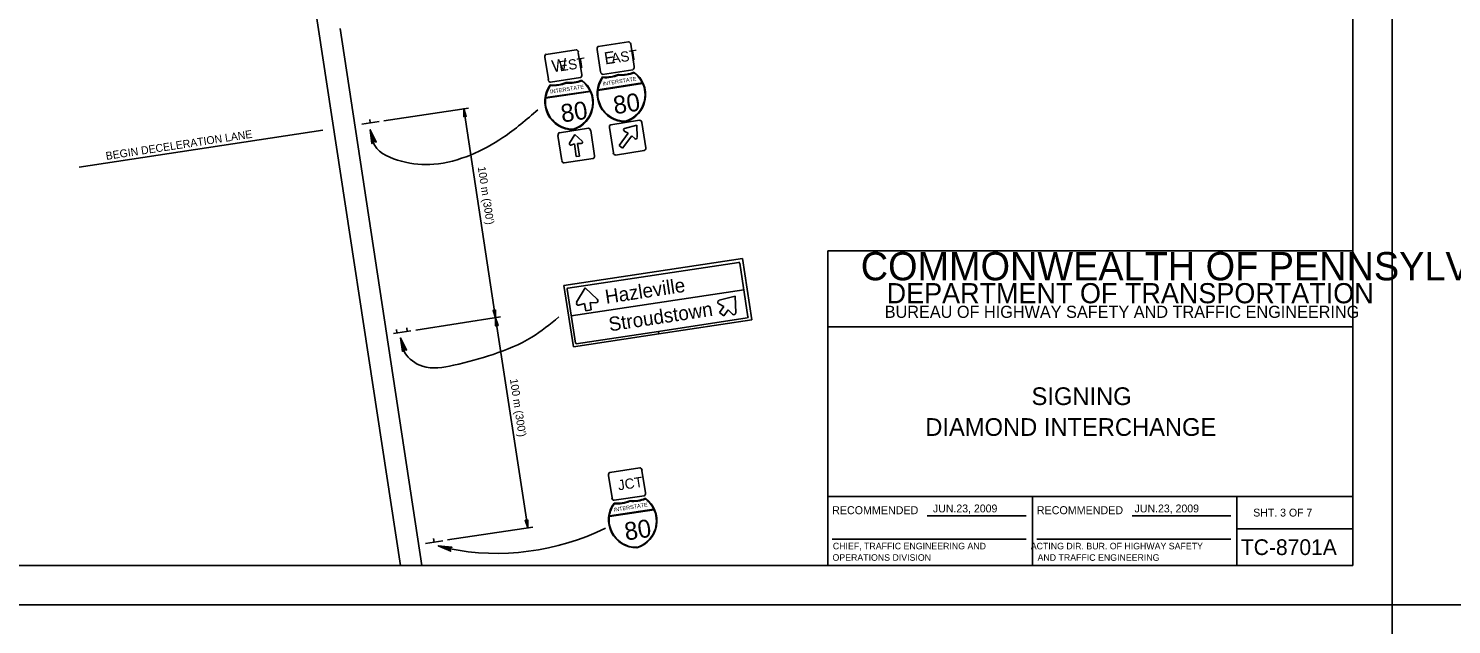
# Model space of a CAD drawing. Extents: x 640994 to 644422, y 298458 to 299646.
# Drawn here: x 642998 to 643540, y 299044 to 299271 of the extents above; entities that cross this region are included whole.
import ezdxf

# ---------------------------------------------------------------- set-up
doc = ezdxf.new("R2010")
doc.units = 0
for name, color, linetype in [('1', 7, 'Continuous'), ('2', 7, 'Continuous'), ('PLT-BNDY', 7, 'Continuous'), ('XCS-GRID-MIN', 7, 'Continuous')]:
    doc.layers.add(name, color=color, linetype=linetype)

msp = doc.modelspace()

# ---------------------------------------------------------------- linework, layer by layer
at = {"layer": '1'}
for p, q in [((643502.31, 299066.63), (643502.31, 299630.63)), ((643302.31, 299066.63), (643302.31, 299186.63)), ((643302.31, 299186.63), (643502.31, 299186.63)), ((643502.31, 299157.63), (643302.31, 299157.63)), ((643302.31, 299093), (643502.31, 299093)), ((643380.31, 299093), (643380.31, 299066.63)), ((643458.19, 299066.63), (643458.19, 299093)), ((643340.24, 299085.57), (643377.87, 299085.57)), ((643418.24, 299085.57), (643455.87, 299085.57)), ((643458.19, 299080.63), (643502.31, 299080.63)), ((643303.99, 299076.68), (643377.87, 299076.68)), ((643381.99, 299076.68), (643455.87, 299076.68)), ((643502.31, 299066.63), (642716.31, 299066.63)), ((642716.31, 299066.63), (643302.31, 299066.63))]:
    msp.add_line(p, q, dxfattribs=at)
at = {"layer": '2'}
for p, q in [((643102.81, 299307.63), (643139.56, 299066.63)), ((643116.56, 299271.38), (643147.69, 299066.63)), ((643195.06, 299261.5), (643206.56, 299263.25)), ((643207.31, 299262.25), (643208.69, 299253.75)), ((643215.81, 299254.88), (643214.56, 299263.38)), ((643214.94, 299264.5), (643226.44, 299266.25)), ((643227.31, 299265.38), (643228.56, 299256.88)), ((643195.94, 299251.88), (643194.56, 299260.38)), ((643201.56, 299257.13), (643201.56, 299257.13)), ((643221.56, 299260.13), (643221.56, 299260.13)), ((643208.19, 299252.63), (643196.69, 299250.88)), ((643208.69, 299251.38), (643208.69, 299251.38)), ((643228.06, 299255.63), (643216.56, 299253.88)), ((643216.69, 299252.63), (643216.69, 299252.63)), ((643222.56, 299253.63), (643222.56, 299253.63)), ((643228.56, 299254.5), (643228.56, 299254.5)), ((643194.81, 299244.75), (643211.94, 299247.38)), ((643211.81, 299247.5), (643194.94, 299245)), ((643196.81, 299249.63), (643196.81, 299249.63)), ((643202.69, 299250.5), (643202.69, 299250.5)), ((643231.69, 299250.63), (643214.81, 299248)), ((643214.81, 299247.75), (643231.81, 299250.38)), ((643133.31, 299236.13), (643165.56, 299241)), ((643175.81, 299161), (643163.69, 299240.75)), ((643204.06, 299241.75), (643204.06, 299241.75)), ((643223.94, 299244.75), (643223.94, 299244.75)), ((643131.44, 299235.88), (643124.81, 299234.88)), ((643128.06, 299235.38), (643127.94, 299236.63)), ((643219.69, 299234.63), (643230.69, 299236.38)), ((643231.56, 299235.5), (643233.06, 299225.88)), ((643017.19, 299218.5), (643110.06, 299232.63)), ((643122.19, 299234.38), (643122.19, 299234.38)), ((643201.06, 299221), (643199.56, 299230.63)), ((643200.19, 299231.63), (643211.19, 299233.38)), ((643203.94, 299227.63), (643205.94, 299231)), ((643205.94, 299231), (643203.94, 299227.63)), ((643205.94, 299231), (643208.81, 299228.38)), ((643208.81, 299228.38), (643205.94, 299231)), ((643212.06, 299232.5), (643213.44, 299222.88)), ((643220.69, 299224), (643219.19, 299233.63)), ((643226.31, 299231.5), (643222.94, 299226.75)), ((643224.19, 299225.75), (643227.69, 299230.5)), ((643224.81, 299232.25), (643226.31, 299231.5)), ((643229.56, 299234.5), (643224.94, 299233.25)), ((643226.06, 299229.75), (643226.06, 299229.75)), ((643227.69, 299230.5), (643228.81, 299229.38)), ((643229.69, 299229.75), (643229.56, 299234.5)), ((643205.81, 299227.38), (643204.44, 299226.88)), ((643204.44, 299226.88), (643205.81, 299227.38)), ((643206.56, 299222.5), (643205.81, 299227.38)), ((643205.81, 299227.38), (643206.56, 299222.5)), ((643208.44, 299227.5), (643207.06, 299227.5)), ((643207.06, 299227.5), (643207.81, 299222.75)), ((643207.81, 299222.75), (643207.06, 299227.5)), ((643207.06, 299227.5), (643208.44, 299227.5)), ((643232.44, 299224.88), (643221.44, 299223.13)), ((643222.94, 299226.75), (643224.19, 299225.75)), ((643212.94, 299221.75), (643201.94, 299220.13)), ((643207.81, 299222.75), (643206.56, 299222.5)), ((643206.56, 299222.5), (643207.81, 299222.75)), ((643269.81, 299183.63), (643201.81, 299173.38)), ((643203.31, 299172.38), (643268.44, 299182.13)), ((643268.81, 299181.88), (643271.94, 299161.38)), ((643273.44, 299160.25), (643269.81, 299183.63)), ((643201.81, 299173.38), (643205.44, 299150)), ((643206.19, 299151.38), (643203.06, 299172)), ((643204.56, 299161.88), (643270.31, 299171.75)), ((643209.94, 299172.5), (643206.69, 299167)), ((643209.94, 299172.5), (643206.69, 299167)), ((643214.56, 299168.13), (643209.94, 299172.5)), ((643214.56, 299168.13), (643209.94, 299172.5)), ((643207.56, 299165.88), (643209.69, 299166.5)), ((643207.56, 299165.88), (643209.69, 299166.5)), ((643209.69, 299166.5), (643210.19, 299163.75)), ((643209.69, 299166.5), (643210.19, 299163.75)), ((643212.19, 299164.13), (643211.81, 299166.88)), ((643211.81, 299166.88), (643214.06, 299166.75)), ((643212.19, 299164.13), (643211.81, 299166.88)), ((643211.81, 299166.88), (643214.06, 299166.75)), ((643237.56, 299166.75), (643237.56, 299166.75)), ((643262.81, 299165.38), (643260.81, 299166.38)), ((643262.81, 299165.38), (643260.81, 299166.38)), ((643260.94, 299167.75), (643267.06, 299169.38)), ((643260.94, 299167.75), (643267.06, 299169.38)), ((643267.06, 299169.38), (643260.94, 299167.75)), ((643260.94, 299167.75), (643267.06, 299169.38)), ((643260.94, 299167.75), (643267.06, 299169.38)), ((643267.06, 299169.38), (643260.94, 299167.75)), ((643261.06, 299163.13), (643262.81, 299165.38)), ((643261.06, 299163.13), (643262.81, 299165.38)), ((643267.06, 299169.38), (643267.31, 299163)), ((643267.06, 299169.38), (643267.31, 299163)), ((643145.44, 299156.38), (643177.69, 299161.38)), ((643188.06, 299081), (643175.81, 299161)), ((643210.19, 299163.75), (643212.19, 299164.13)), ((643210.19, 299163.75), (643212.19, 299164.13)), ((643271.69, 299161), (643237.87, 299155.87)), ((643238.02, 299154.91), (643273.44, 299160.25)), ((643262.81, 299161.88), (643261.06, 299163.13)), ((643262.81, 299161.88), (643261.06, 299163.13)), ((643264.44, 299164.13), (643262.81, 299161.88)), ((643264.44, 299164.13), (643262.81, 299161.88)), ((643266.06, 299162.5), (643264.44, 299164.13)), ((643266.06, 299162.5), (643264.44, 299164.13)), ((643266.06, 299162.5), (643266.06, 299162.5)), ((643134.31, 299154.75), (643134.31, 299154.75)), ((643143.56, 299156.13), (643136.94, 299155.13)), ((643138.19, 299155.38), (643138.06, 299156.63)), ((643142.19, 299155.88), (643142.06, 299157.25)), ((643205.44, 299150), (643238.02, 299154.91)), ((643237.87, 299155.87), (643206.56, 299151.13)), ((643237.87, 299155.87), (643238.02, 299154.91)), ((643238.02, 299154.91), (643237.87, 299155.87)), ((643220.19, 299092.5), (643218.81, 299101)), ((643219.31, 299102.13), (643230.81, 299103.88)), ((643231.56, 299102.88), (643232.94, 299094.38)), ((643225.81, 299097.63), (643225.81, 299097.63)), ((643232.44, 299093.25), (643220.94, 299091.5)), ((643221.06, 299090.25), (643221.06, 299090.25)), ((643226.94, 299091.13), (643226.94, 299091.13)), ((643232.94, 299092), (643232.94, 299092)), ((643236.06, 299088.13), (643219.19, 299085.63)), ((643219.19, 299085.38), (643236.19, 299087.88)), ((643157.56, 299076.38), (643189.94, 299081.25)), ((643146.44, 299075), (643146.44, 299075)), ((643146.44, 299074.63), (643146.44, 299074.63)), ((643155.69, 299076), (643149.06, 299075)), ((643152.44, 299075.5), (643152.19, 299076.88))]:
    msp.add_line(p, q, dxfattribs=at)
for points in [[(643163.76, 299237.88), (643163.95, 299238.01), (643163.69, 299240.75), (643163.76, 299237.88), (643163.66, 299237.71), (643163.69, 299240.75), (643164.23, 299238.06), (643164.45, 299237.99), (643163.69, 299240.75), (643164.61, 299237.86), (643164.45, 299237.99)], [(643128.81, 299227.88), (643129.06, 299228.13), (643128.06, 299232.75), (643128.81, 299227.88), (643128.69, 299227.5), (643128.06, 299232.75), (643129.56, 299228.25), (643129.94, 299228.25), (643128.06, 299232.75), (643130.31, 299228), (643129.94, 299228.25)], [(643175.74, 299163.88), (643175.55, 299163.74), (643175.81, 299161), (643175.74, 299163.88), (643175.84, 299164.04), (643175.81, 299161), (643175.27, 299163.7), (643175.05, 299163.76), (643175.81, 299161), (643174.89, 299163.9), (643175.05, 299163.76)], [(643175.89, 299158.13), (643176.08, 299158.26), (643175.81, 299161), (643175.89, 299158.13), (643175.79, 299157.96), (643175.81, 299161), (643176.36, 299158.31), (643176.58, 299158.24), (643175.81, 299161), (643176.74, 299158.11), (643176.58, 299158.24)], [(643140.44, 299148.5), (643140.81, 299148.75), (643139.56, 299153.38), (643140.44, 299148.5), (643140.31, 299148.25), (643139.56, 299153.38), (643141.19, 299149), (643141.56, 299148.88), (643139.56, 299153.38), (643141.94, 299148.75), (643141.56, 299148.88)], [(643187.98, 299083.88), (643187.8, 299083.74), (643188.06, 299081), (643187.98, 299083.88), (643188.09, 299084.04), (643188.06, 299081), (643187.51, 299083.69), (643187.3, 299083.76), (643188.06, 299081), (643187.14, 299083.89), (643187.3, 299083.76)], [(643158.51, 299072.37), (643158.39, 299072.74), (643153.96, 299074.16), (643158.51, 299072.37), (643158.73, 299072.06), (643153.96, 299074.16), (643158.54, 299073.16), (643158.77, 299073.49), (643153.96, 299074.16), (643159.15, 299073.61), (643158.77, 299073.49)]]:
    msp.add_lwpolyline(points, dxfattribs=at)
for centre, radius, start, end in [((643203.86, 299263.04), 12.33, 264.4038, 292.9038), ((643203.86, 299263.04), 12.56, 264.6648, 292.3133), ((643202.3, 299243.04), 10.73, 286.7839, 53.6538), ((643202.3, 299243.04), 10.51, 25.4466, 52.9614), ((643225.23, 299246.52), 10.73, 143.6538, 270.5237), ((643225.23, 299246.52), 10.51, 144.3462, 171.8611), ((643217.79, 299265.16), 12.33, 264.4038, 292.9038), ((643217.79, 299265.16), 12.56, 264.9943, 292.6428), ((643223.79, 299266.07), 12.33, 264.4038, 292.9038), ((643223.79, 299266.07), 12.56, 264.6648, 292.3133), ((643222.23, 299246.07), 10.73, 286.7839, 53.6538), ((643222.23, 299246.07), 10.51, 25.4466, 52.9614), ((643205.3, 299243.49), 10.73, 143.6538, 270.5237), ((643205.3, 299243.49), 10.51, 144.3462, 171.8611), ((643197.86, 299262.12), 12.33, 264.4038, 292.9038), ((643197.86, 299262.12), 12.56, 264.9943, 292.6428), ((643202.3, 299243.04), 10.51, 286.7839, 24.1669), ((643225.23, 299246.52), 10.51, 173.1407, 270.5237), ((643222.23, 299246.07), 10.51, 286.7839, 24.1669), ((643205.3, 299243.49), 10.51, 173.1407, 270.5237), ((643225.07, 299232.74), 0.5, 103.9183, 245.5492), ((643229.19, 299229.7), 0.5, 225, 1.3737), ((643204.37, 299227.38), 0.46, 148.5129, 289.1785), ((643204.37, 299227.38), 0.46, 148.5129, 289.1785), ((643208.49, 299227.98), 0.46, 266.9014, 50.808), ((643208.49, 299227.98), 0.46, 266.9014, 50.8081), ((643268.53, 299181.93), 0.309, 7.3907, 98.4613), ((643203.39, 299172.11), 0.309, 98.9487, 188.5961), ((643207.4, 299166.56), 0.745, 148.5129, 289.1785), ((643207.4, 299166.56), 0.745, 148.5129, 289.1785), ((643214.08, 299167.54), 0.745, 266.9014, 50.8081), ((643214.08, 299167.54), 0.745, 266.9014, 50.8081), ((643261.15, 299167), 0.745, 103.5129, 244.1785), ((643261.15, 299167), 0.745, 103.5129, 244.1785), ((643266.57, 299162.97), 0.745, 221.9014, 5.8081), ((643266.57, 299162.97), 0.745, 221.9014, 5.8081), ((643271.71, 299161.4), 0.309, 278.3685, 10.1781), ((643206.58, 299151.55), 0.309, 189.1727, 276.4437), ((643229.56, 299084.08), 10.73, 143.6538, 270.5237), ((643229.56, 299084.08), 10.51, 144.3462, 171.8611), ((643222.12, 299102.71), 12.33, 264.4038, 292.9038), ((643222.12, 299102.71), 12.56, 264.9943, 292.6428), ((643228.12, 299103.62), 12.33, 264.4038, 292.9038), ((643228.12, 299103.62), 12.56, 264.6648, 292.3133), ((643226.56, 299083.62), 10.73, 286.7839, 53.6538), ((643226.56, 299083.62), 10.51, 25.4466, 52.9614), ((643229.56, 299084.08), 10.51, 173.1407, 270.5237), ((643226.56, 299083.62), 10.51, 286.7839, 24.1669), ((643176.31, 299165.19), 93.92, 258.636, 296.1278)]:
    msp.add_arc(centre, radius, start, end, dxfattribs=at)
for centre, major_axis, ratio, start_param, end_param in [((643206.7, 299262.21), (-0.16, 1.06), 0.6, 4.712389, 6.283185), ((643215.15, 299263.5), (0.16, -1.06), 0.6, 3.141593, 4.712389), ((643226.63, 299265.25), (-0.16, 1.06), 0.6, 4.712389, 6.283185), ((643195.22, 299260.47), (0.16, -1.06), 0.6, 3.141593, 4.712389), ((643227.92, 299256.74), (-0.16, 1.06), 0.6, 3.141593, 4.712389), ((643196.51, 299251.96), (0.16, -1.06), 0.6, 4.712389, 6.283185), ((643207.99, 299253.71), (-0.16, 1.06), 0.6, 3.141593, 4.712389), ((643216.44, 299255), (0.16, -1.06), 0.6, 4.712389, 6.283185), ((643230.85, 299235.42), (-0.14, 0.921), 0.769266, 4.712389, 6.283185), ((643200.32, 299230.73), (0.14, -0.921), 0.769266, 3.141593, 4.712389), ((643211.3, 299232.4), (-0.14, 0.921), 0.769266, 4.712389, 6.283185), ((643219.86, 299233.75), (0.14, -0.921), 0.769266, 3.141593, 4.712389), ((643232.32, 299225.75), (-0.14, 0.921), 0.769266, 3.141593, 4.712389), ((643201.79, 299221.06), (0.14, -0.921), 0.769266, 4.712389, 6.283185), ((643212.78, 299222.73), (-0.14, 0.921), 0.769266, 3.141593, 4.712389), ((643221.33, 299224.08), (0.14, -0.921), 0.769266, 4.712389, 6.283185), ((643219.48, 299101.05), (0.16, -1.06), 0.6, 3.141593, 4.712389), ((643230.96, 299102.8), (-0.16, 1.06), 0.6, 4.712389, 6.283185), ((643232.25, 299094.3), (-0.16, 1.06), 0.6, 3.141593, 4.712389), ((643220.78, 299092.55), (0.16, -1.06), 0.6, 4.712389, 6.283185)]:
    msp.add_ellipse(centre, major_axis=major_axis, ratio=ratio, start_param=start_param, end_param=end_param, dxfattribs=at)
for points in [[(643191.94, 299240.38), (643178.56, 299229.75), (643166.31, 299223.13), (643152.31, 299219.63), (643139.94, 299220.75), (643129.81, 299226.75), (643128.06, 299232.75)], [(643199.94, 299161.38), (643189.56, 299153.63), (643174.94, 299147.13), (643159.81, 299143), (643147.94, 299142.63), (643141.31, 299147.75), (643139.56, 299153.38)]]:
    msp.add_spline(points, degree=3, dxfattribs=at)
at = {"layer": 'XCS-GRID-MIN'}
for points in [[(642676.31, 299645.63), (643517.31, 299645.63), (643517.31, 299051.63), (642676.31, 299051.63)], [(643517.31, 299645.63), (644358.31, 299645.63), (644358.31, 299051.63), (643517.31, 299051.63)], [(642676.31, 299051.63), (643517.31, 299051.63), (643517.31, 298457.63), (642676.31, 298457.63)]]:
    msp.add_lwpolyline(points, close=True, dxfattribs=at)

# ---------------------------------------------------------------- texts
at = {"layer": '1'}
for s, height, p in [('COMMONWEALTH OF PENNSYLVANIA', 10.7828, (643314.9, 299175.36)), ('DEPARTMENT OF TRANSPORTATION', 7.6837, (643324.76, 299166.61)), ('BUREAU OF HIGHWAY SAFETY AND TRAFFIC ENGINEERING', 4.6253, (643324.04, 299161.04)), ('SIGNING', 6.75, (643379.96, 299127.81)), ('DIAMOND INTERCHANGE', 6.75, (643339.49, 299116.06)), ('RECOMMENDED', 3.048, (643303.99, 299086.2)), ('RECOMMENDED', 3.048, (643381.99, 299086.2)), ('SHT. 3 OF 7', 3, (643464.4, 299085.31)), ('TC-8701A', 6, (643459.68, 299070.63))]:
    msp.add_text(s, height=height, dxfattribs=at).set_placement(p)
at = {"layer": '2'}
for s, height, rotation, p in [('E', 4.63, 8.6525, (643217.56, 299257.63)), ('AST', 3.875, 8.6538, (643220.19, 299258)), ('W', 4.63, 8.6525, (643197.56, 299254.63)), ('EST', 3.875, 8.6538, (643200.31, 299255)), ('INTERSTATE', 1.517, 8.6538, (643216.69, 299249.5)), ('INTERSTATE', 1.517, 8.6538, (643196.69, 299246.5)), ('80', 6.829, 8.6538, (643221.19, 299238.63)), ('80', 6.829, 8.6538, (643201.19, 299235.5)), ('BEGIN DECELERATION LANE', 3, 8.6534, (643027.56, 299221.25)), ("100 m (300')", 3, 278.6536, (643169.01, 299218.53)), ('Hazleville  ', 5.3752, 8.6538, (643217.94, 299166.38)), ('Stroudstown', 5.3752, 8.6538, (643219.31, 299155.88)), ("100 m (300')", 3, 278.6537, (643181.26, 299137.65)), ('JCT', 3.896, 8.6538, (643222.69, 299095.25)), ('INTERSTATE', 1.517, 8.6538, (643220.94, 299087.13)), ('80', 6.829, 8.6538, (643225.44, 299076.13))]:
    msp.add_text(s, height=height, rotation=rotation, dxfattribs=at).set_placement(p)
for p in [(643342.41, 299086.89), (643419.21, 299086.89)]:
    msp.add_text('JUN.23, 2009', height=3, dxfattribs=at).set_placement(p)
at = {"layer": 'PLT-BNDY'}
for s, p in [('CHIEF, TRAFFIC ENGINEERING AND', (643304.28, 299072.81)), ('  ACTING DIR. BUR. OF HIGHWAY SAFETY', (643377.81, 299072.8)), ('  ACTING DIR. BUR. OF HIGHWAY SAFETY', (643377.81, 299072.8)), ('OPERATIONS DIVISION', (643304.14, 299068.44))]:
    msp.add_text(s, height=2.5, dxfattribs=at).set_placement(p)
msp.add_text('AND TRAFFIC ENGINEERING', height=2.5, rotation=360, dxfattribs=at).set_placement((643382.25, 299068.43))
msp.add_text('AND TRAFFIC ENGINEERING', height=2.5, rotation=360, dxfattribs=at).set_placement((643382.25, 299068.43))

doc.saveas('drawing.dxf')
